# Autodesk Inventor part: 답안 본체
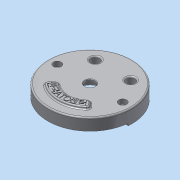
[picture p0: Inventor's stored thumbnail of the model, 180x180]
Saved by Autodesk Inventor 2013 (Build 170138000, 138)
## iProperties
Created: 2015-04
Part Number: 답안 본체
Material: 알루미늄 6061
Document SubType Name: Modeling
Designer: Administrator
Density: 2.71 g/cm^3
Mass: 1268.25 g
Surface Area: 1022 cm^2
Volume: 467.99 cm^3
Author: Administrator
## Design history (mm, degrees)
sketch "스케치1"
  geometry: C1 r 95 at (0, 0); 1 further point
  constraints: 1 centre point, 1 coincident
  dimensions: "d0" = 190 diameter of C1
extrude "돌출1" new body sketch "스케치1" stored distance "d1" = 32; taper "d2" = 0 deg
sketch "스케치2"
  geometry: C1 r 95 at (0, 0) reference; C2 r 90 at (0, 0)
  constraints: 1 centre point, 1 coincident
  dimensions: "d4" = 180 diameter of C2
extrude "돌출2" cut sketch "스케치2" distance "d5" = 21; taper "d6" = 0 deg
sketch "스케치3"
  geometry: L1 (0, 0)-(95, 0); L2 (0, 0)-(0, 95); L3 (0, 0)-(-95, 0); L4 (89.658, -7.844)-(94.638, -8.28); L5 (-89.658, -7.844)-(-94.638, -8.28); A1 r 95 centre (0, 0) between (0, 95) and (95, 0) reference; A2 r 90 centre (0, 0) between (-89.658, -7.844) and (89.658, -7.844); A3 r 95 centre (0, 0) between (-94.638, -8.28) and (94.638, -8.28); 1 further point
  constraints: 10 end point, 8 point on circle, 3 coincident, 2 centre point, 2 perpendicular, 2 symmetric about line, 1 concentric, 1 horizontal, 2 other
  dimensions: "d97" = 5 deg dimension on point (0, 0) L1.end L4.start; "d98" = 5 deg dimension on point (0, 0) L1.end L4.end
extrude "돌출3" cut sketch "스케치3" distance "d12" = 5; taper "d13" = 0 deg
sketch "스케치4"
  geometry: L1 (-89.196, 12)-(-40.249, 12); L2 (40.249, 12)-(89.196, 12); A1 r 90 centre (0, 0) between (-89.196, 12) and (89.196, 12) reference; A2 r 42 centre (0, 0) between (40.249, 12) and (-40.249, 12)
  constraints: 4 end point, 4 point on circle, 2 horizontal, 1 centre point, 1 coincident, 1 collinear
  dimensions: "d14" = 84 diameter of A2; "d16" = 12 distance from line of A1.centre L2
extrude "돌출4" join sketch "스케치4" stored distance "d17" = 5; taper "d18" = 0 deg
sketch "스케치19"
  geometry: L1 (-94.638, -8.28)-(-89.658, -7.844) reference; L2 (-89.196, 12)-(-40.249, 12) reference; L3 (40.249, 12)-(89.196, 12) reference; L4 (89.658, -7.844)-(94.638, -8.28) reference; L5 (-40.249, 12)-(-89.196, 12); L6 (40.249, 12)-(89.196, 12); A1 r 42 centre (0, 0) between (40.249, 12) and (-40.249, 12) reference; A2 r 95 centre (0, 0) between (94.638, -8.28) and (-94.638, -8.28) reference; A3 r 90 centre (0, 0) between (89.196, 12) and (-89.196, 12); A4 r 42 centre (0, 0) between (40.249, 12) and (-40.249, 12)
  constraints: 8 end point, 5 point on circle, 2 centre point, 2 coincident, 2 collinear, 2 point on line, 1 concentric
extrude "돌출18" cut sketch "스케치19" distance "d99" = 25; taper "d100" = 0 deg
sketch "스케치6"
  geometry: C1 r 35 at (0, 0); A1 r 90 centre (0, 0) between (-89.196, 12) and (89.196, 12) reference
  constraints: 1 centre point, 1 coincident
  dimensions: "d21" = 70 diameter of C1
extrude "돌출6" join sketch "스케치6" distance "d22" = 10; taper "d23" = -10 deg
sketch "스케치7"
  geometry: C1 r 33.237 at (0, 0) reference; C2 r 25 at (0, 0)
  constraints: 1 centre point, 1 coincident
  dimensions: "d24" = 50 diameter of C2
extrude "돌출7" cut sketch "스케치7" distance "d25" = 15; taper "d26" = 0 deg
sketch "스케치8"
  geometry: C1 r 25 at (0, 0) reference; C2 r 11.5 at (0, 0)
  constraints: 1 centre point, 1 coincident
  dimensions: "d27" = 23 diameter of C2
extrude "돌출8" cut sketch "스케치8" stored distance "d28" = 15; taper "d29" = 0 deg
sketch "스케치15"
  geometry: C1 r 35 at (0, 0) reference; A1 r 59 centre (0, -19) between (-58.704, -13.1) and (58.704, -13.1); A2 r 41 centre (0, -19) between (-40.794, -14.9) and (40.794, -14.9); A3 r 9 centre (49.749, -14) between (58.704, -13.1) and (40.794, -14.9); A4 r 9 centre (-49.749, -14) between (-40.794, -14.9) and (-58.704, -13.1)
  constraints: 8 point on circle, 4 centre point, 2 tangent, 1 coincident, 1 horizontal alignment, 1 vertical alignment
  dimensions: "d59" = 118 diameter of A1; "d60" = 19 distance of C1.centre A1.centre; "d61" = 82 diameter of A2; "d62" = 18 diameter of A3; "d63" = 5 vertical distance of A2.centre A3.centre; "d64" = 18 diameter of A4
extrude "돌출15" cut sketch "스케치15" distance "d65" = 7; taper "d66" = 0 deg
fillet "모깎기3" dims "d69" = 1
fillet "모깎기4" dims "d70" = 3
chamfer "모따기1" distance "d72" = 1; stored, may be unused: second distance "d73" = 2, angle "d74" = 45 deg
fillet "모깎기6" dims "d78" = 3
sketch "스케치16"
  geometry: L1 (0, 0)-(-50.912, -50.912); L2 (0, 0)-(0, -72); L3 (0, 0)-(50.912, -50.912); L4 (50.912, -50.912)-(36.062, -36.062); L5 (-50.912, -50.912)-(-36.062, -36.062); C1 r 12.5 at (0, 0) reference; A1 r 72 centre (0, 0) between (-50.912, -50.912) and (50.912, -50.912); A2 r 51 centre (0, 0) between (-36.062, -36.062) and (36.062, -36.062)
  constraints: 10 end point, 5 point on circle, 2 centre point, 2 coincident, 2 point on line, 1 vertical
  dimensions: "d81" = 144 diameter of A1; "d82" = 102 diameter of A2; "d83" = 45 deg angle of L1 L2; "d84" = 45 deg angle of L2 L3
extrude "돌출16" join sketch "스케치16" distance "d85" = 5; taper "d86" = 0 deg
sketch "스케치17"
  geometry: C1 r 68 at (0, 0); A1 r 51 centre (0, 0) between (-36.062, -36.062) and (36.062, -36.062) reference
  constraints: 1 centre point, 1 coincident, 1 other
  dimensions: "d87" = 136 diameter of C1
feature "엠보싱1" sketch "스케치17" dims "d0" = 190, "d88" = 0.5, "d89" = 0
fillet "모깎기7" dims "d90" = 5
fillet "모깎기8" dims "d91" = 3
sketch "스케치20"
  geometry: C1 r 15 at (40, 52); C2 r 15 at (-40, 52); A1 r 42 centre (0, 0) between (40.249, 12) and (-40.249, 12) reference
  constraints: 2 centre point
  dimensions: "d101" = 30 diameter of C1; "d103" = 52 vertical distance of A1.centre C1.centre; "d104" = 40 horizontal distance of C1.centre A1.centre; "d105" = 30 diameter of C2; "d106" = 40 horizontal distance of A1.centre C2.centre; "d107" = 52 vertical distance of A1.centre C2.centre
extrude "돌출19" join sketch "스케치20" stored distance "d108" = 25; taper "d109" = 0 deg
sketch "스케치21"
  geometry: C1 r 15 at (0, 0) reference; C2 r 10 at (0, 0); C3 r 15 at (80, 0) reference; C4 r 10 at (80, 0); 1 further point
  constraints: 2 centre point, 2 coincident
  dimensions: "d110" = 20 diameter of C2; "d111" = 20 diameter of C4
extrude "돌출20" cut sketch "스케치21" stored distance "d112" = 25; taper "d113" = 0 deg
sketch "스케치22"
  geometry: L1 (13.748, 6)-(-13.748, 6); L2 (-13.748, -6)-(13.748, -6); L3 (66.252, 6)-(93.748, 6); L4 (93.748, -6)-(66.252, -6); C1 r 10 at (0, 0) reference; C2 r 10 at (80, 0) reference; A1 r 15 centre (0, 0) between (13.748, 6) and (-13.748, 6) reference; A2 r 15 centre (80, 0) between (66.252, 6) and (93.748, 6) reference; 1 further point
  constraints: 8 end point, 8 point on circle, 3 parallel, 1 horizontal
  dimensions: "d115" = 6 distance from line of L1 C1.centre; "d116" = 6 distance from line of L2 C1.centre; "d117" = 6 distance from line of L4 C2.centre; "d118" = 6 distance from line of C2.centre L3
extrude "돌출21" cut sketch "스케치22" distance "d119" = 3; taper "d120" = 0 deg
sketch "스케치24"
  geometry: L1 (-6, 13.748)-(-6, -13.748); L2 (6, -13.748)-(6, 13.748); C1 r 10 at (0, 0) reference; A1 r 15 centre (0, 0) between (-6, 13.748) and (-6, -13.748) reference; 1 further point
  constraints: 4 end point, 4 point on circle, 1 parallel, 1 vertical
  dimensions: "d122" = 6 distance from line of C1.centre L1; "d123" = 6 distance from line of L2 C1.centre
extrude "돌출22" cut sketch "스케치24" distance "d124" = 3; taper "d125" = 0 deg
fillet "모깎기10" dims "d126" = 3
fillet "모깎기11" dims "d127" = 10
fillet "모깎기12" dims "d128" = 3
fillet "모깎기13" dims "d129" = 3
fillet "모깎기14" dims "d130" = 0.3
sketch "스케치25"
  geometry: C1 r 35 at (0, 0) reference; C2 r 9 at (74, 0); C3 r 9 at (-74, 0); A1 r 87 centre (0, 0) between (-85.385, 16.684) and (85.385, 16.684) reference; A2 r 74 centre (0, 0) between (74, 0) and (-74, 0)
  constraints: 3 centre point, 2 horizontal alignment, 2 point on circle, 1 coincident
  dimensions: "d131" = 148 diameter of A2; "d132" = 18 diameter of C2; "d133" = 18 diameter of C3
extrude "돌출23" join sketch "스케치25" stored distance "d134" = 11; taper "d135" = 0 deg
sketch "스케치26"
  geometry: L1 (-41.561, -37.319)-(-49.365, -45.123) reference; L2 (49.365, -45.123)-(41.561, -37.319) reference; C1 r 9 at (74, 0) reference; C2 r 13 at (-40, 52) reference; C3 r 12.5 at (0, 0) reference; C4 r 92 at (0, 0) reference; C5 r 13 at (40, 52) reference; C6 r 9 at (-74, 0) reference; A1 r 8 centre (-35.904, -42.975) between (-30.775, -36.836) and (-41.561, -37.319) reference; A2 r 48 centre (0, 0) between (-30.775, -36.836) and (30.775, -36.836) reference; A3 r 8 centre (35.904, -42.975) between (41.561, -37.319) and (30.775, -36.836) reference; A4 r 8 centre (43.709, -50.78) between (48.927, -56.843) and (49.365, -45.123) reference; A5 r 75 centre (0, 0) between (-48.927, -56.843) and (48.927, -56.843) reference; A6 r 8 centre (-43.709, -50.78) between (-49.365, -45.123) and (-48.927, -56.843) reference; 2 further points
  constraints: 2 coincident
hole "구멍1" sketch "스케치26" at (-74, 0), (74, 0) diameter "d136" = 11; stored, may be unused: countersink angle "d140" = 90 deg, drill point angle "d142" = 118 deg; dims "d137" = 6, "d138" = 18, "d139" = 11, "d141" = 8
fillet "모깎기15" dims "d143" = 3
fillet "모깎기16" dims "d144" = 3
node "솔리드1"
node "투영된 루프3"
node "투영된 루프4"
node "투영된 루프5"
other parameters: "d15" = 12
